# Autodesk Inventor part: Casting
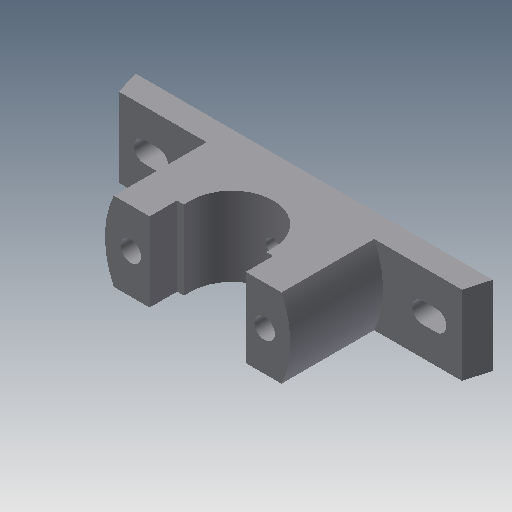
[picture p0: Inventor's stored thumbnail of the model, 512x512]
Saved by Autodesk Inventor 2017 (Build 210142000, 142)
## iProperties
Created: 2009-04
Part Number: Casting
Document SubType Name: Modeling
Designer: Sham
Density: 1 g/cm^3
Material: Generic
Appearance: Default
Author: Sham
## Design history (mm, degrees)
sketch "Sketch1"
  geometry: L1 (-104, 0)-(104, 0); L2 (-104, 0)-(-100, 14); L3 (-100, 14)-(100, 14); L4 (100, 14)-(104, 0); 1 further point
  constraints: 8 end point, 1 horizontal, 1 midpoint, 1 parallel, 1 other
  dimensions: "d0" = 208 distance of L1.start L1.end; "d1" = 104 distance of L1.end point (0, 0); "d2" = 4 horizontal distance of L1.start L2.end; "d3" = 4 horizontal distance of L1.end L3.end; "d10" = 14 distance between parallel lines of L1 L3
extrude "Extrusion1" new body sketch "Sketch1" stored distance "d4" = 46; taper "d5" = 0 deg
sketch "Sketch2"
  geometry: L1 (51.143, 46)-(148.857, 46); L2 (148.857, 0)-(51.143, 0); A1 r 54 centre (100, 23) between (51.143, 46) and (51.143, 0); A2 r 54 centre (100, 23) between (148.857, 0) and (148.857, 46)
  constraints: 4 end point, 4 point on circle, 2 centre point, 1 parallel
extrude "Extrusion2" join sketch "Sketch2" distance "d8" = 54; taper "d9" = 0 deg
sketch "Sketch3"
  geometry: L1 (-28, 68)-(-28, 52); L2 (-28, 52)-(-24, 52); L3 (28, 68)-(28, 52); L4 (28, 52)-(24, 52); L5 (-28, 68)-(28, 68); L6 (-100, 14)-(-48.857, 14) reference; L7 (0, 48)-(0, 19); L8 (48.857, 14)-(100, 14) reference; L9 (48.857, 68)-(-48.857, 68) reference; L10 (-24, 48)-(-24, 52); L11 (24, 48)-(24, 52); A1 r 24 centre (0, 48) between (-24, 48) and (24, 48); 1 further point
  constraints: 16 end point, 5 perpendicular, 2 point on circle, 2 symmetric about line, 1 centre point, 1 tangent, 1 vertical alignment, 1 other
  dimensions: "d11" = 16 distance of L1.start L1.end; "d16" = 24 radius of A1; "d17" = 16 distance of L3.start L3.end; "d52" = 56 distance between parallel lines of L1 L3; "d54" = 54 distance between parallel lines of L8 L9 (derived)
extrude "Extrusion3" cut sketch "Sketch3" distance "d18" = 54; taper "d19" = 0 deg
sketch "Sketch4"
  geometry: L1 (-23, 29)-(-15, 29); L2 (-15, 17)-(-23, 17); L3 (-185, 29)-(-177, 29); L4 (-177, 17)-(-185, 17); A1 r 6 centre (-15, 23) between (-15, 17) and (-15, 29); A2 r 6 centre (-23, 23) between (-23, 29) and (-23, 17); A3 r 6 centre (-177, 23) between (-177, 17) and (-177, 29); A4 r 6 centre (-185, 23) between (-185, 29) and (-185, 17)
  constraints: 8 end point, 8 point on circle, 8 tangent, 4 centre point, 3 parallel
  dimensions: "d20" = 8 distance of A1.centre A2.centre; "d21" = 6 radius of A1; "d24" = 6 radius of A3; "d25" = 8 distance of A4.centre A3.centre
extrude "Extrusion4" cut sketch "Sketch4" distance "d28" = 54; taper "d29" = 0 deg
sketch "Sketch5"
  geometry: L1 (208, 0)-(0, 0) reference; L2 (52, -10)-(78, -10); L3 (78, -10)-(78, -36); L4 (78, -36)-(52, -36); L5 (52, -36)-(52, -10); L6 (130, -10)-(156, -10); L7 (156, -10)-(156, -36); L8 (156, -36)-(130, -36); L9 (130, -36)-(130, -10); L10 (0, -46)-(208, -46) reference; L11 (104, -23)-(104, -46)
  constraints: 18 end point, 5 perpendicular, 4 parallel, 2 horizontal, 1 midpoint
  dimensions: "d30" = 26 distance of L2.start L2.end; "d31" = 10 distance between parallel lines of L2 L1; "d32" = 10 distance between parallel lines of L1 L6; "d65" = 26 distance between parallel lines of L3 L11; "d66" = 26 distance between parallel lines of L9 L11
extrude "Extrusion5" cut sketch "Sketch5" distance "d34" = 10; taper "d35" = 0 deg
sketch "Sketch6"
  geometry: L1 (148.857, 0)-(128, 0) reference; L2 (72, 0)-(51.143, 0) reference; L3 (0, 46)-(0, 0) reference; L4 (200, 46)-(200, 0) reference; C1 r 6 at (61, 23); C2 r 6 at (139, 23); 1 further point
  constraints: 2 centre point, 1 equal radius
  dimensions: "d36" = 12 diameter of C1; "d37" = 78 distance of C2.centre C1.centre; "d39" = 39 distance of C2.centre point (100, 23); "d58" = 39 distance of C1.centre point (100, 23); "d59" = 23 distance from line of L1 C2.centre; "d60" = 23 distance from line of L2 C1.centre; "d61" = 61 distance from line of L3 C1.centre; "d62" = 61 distance from line of L4 C2.centre (derived)
extrude "Extrusion6" cut sketch "Sketch6" stored distance "d40" = 10; taper "d41" = 0 deg
workplane "Work Plane1"
sketch "Sketch7"
  geometry: L1 (-4, 46)-(204, 46) reference; L2 (-4, 0)-(-4, 46) reference; 1 further point
  dimensions: "d43" = 23 distance from line of L1 point (100, 23); "d44" = 104 distance from line of point (100, 23) L2
hole "Hole1" sketch "Sketch7" at (100, 23) diameter "d45" = 8; stored, may be unused: countersink angle "d49" = 90 deg, drill point angle "d51" = 118 deg; dims "d46" = 6, "d47" = 8, "d48" = 16, "d50" = 8
body "Solid1"
other parameters: "d6" = 108, "d42" = -52
